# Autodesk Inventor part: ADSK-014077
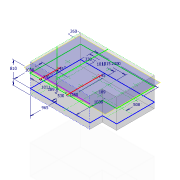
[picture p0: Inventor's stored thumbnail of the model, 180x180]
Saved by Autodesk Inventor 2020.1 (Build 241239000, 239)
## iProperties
Created: 2019-10
Part Number: ADSK-014077
Material: 1.0501 C35
Document SubType Name: Modeling
Designer: lutzd
Mass: 3.8576e+07 g
Surface Area: 188642 cm^2
Volume: 4.9204e+06 cm^3
Density: 7.84 g/cm^3
Appearance: Klar - Weiß
VLDS_Profile: Default Part
VLDS_TimeStamp: 2016-07-29
VLDS_FailCnt: 0
VLDS_AcceptCnt: 0
Dimensions: 2690x1830x1050 mm
Mass: 38575,975 kg
DocNumber: ADSK-014077
Folder: 01 - Themengebiete\Simplification\01 - Packaging machine\
VDS_Category: 3D Komponenten
VDS_NumSchm: Autodesk
Title: skeleton
Author: lutzd
Revision Number: -
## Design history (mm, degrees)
sketch "Skizze1"
  geometry: L1 (0, 0)-(0, 1830); L2 (0, 1830)-(2690, 1830); L3 (2690, 1830)-(2690, 455); L4 (2690, 455)-(2170, 455); L5 (2170, 455)-(2170, 0); L6 (2170, 0)-(0, 0)
  constraints: 12 end point, 5 perpendicular, 1 vertical
  dimensions: "d0" = 2690 distance of L1.end L2.end; "d1" = 1830 distance of L1.start L1.end; "d2" = 520 distance of L3.end L4.end; "d3" = 455 distance of L4.end L5.end
extrude "Extrusion1" new body sketch "Skizze1" distance "d4" = 1050; taper "d5" = 0 deg
sketch "Skizze2" dims "d12" = 1011
  geometry: L1 (0, 1050)-(2170, 1050) reference; L2 (0, 0)-(2170, 0) reference; L3 (2170, 0)-(2170, 1050) reference; L4 (0, 0)-(0, 1050) reference; L5 (0, 810)-(2170, 810); 1 further point
  constraints: 3 point on line, 2 end point, 1 perpendicular
  dimensions: "d24" = 810 distance between parallel lines of L5 L2; "d26" = 1011 distance from line of L4 point (1011, 810)
workplane "Arbeitsebene1"
sketch "Skizze4" dims "d12" = 1011
  geometry: L1 (1050, 1830)-(1050, 0) reference; L2 (0, 1830)-(0, 0) reference; L3 (1050, 965)-(0, 965); L4 (0, 0)-(1050, 0) reference
  constraints: 2 end point, 2 point on line, 1 perpendicular
  dimensions: "d14" = 965 distance between parallel lines of L4 L3
sketch "Skizze3"
  geometry: L1 (0, 0)-(-2170, 0) reference; L2 (-2170, 0)-(-2170, 455) reference; L3 (-2170, 455)-(-2690, 455) reference; L4 (-2690, 455)-(-2690, 1830) reference; L5 (-2690, 1830)-(0, 1830) reference; L6 (0, 1830)-(0, 0) reference; L7 (-330, 1830)-(-330, 0); L8 (-1315, 1830)-(-1315, 0); L9 (-2300, 1830)-(-2300, 1038); L10 (-330, 530)-(-1315, 530); L11 (-1011, 530)-(-1011, 1830); L12 (-1315, 1038)-(-2690, 1038); L13 (0, 965)-(-330, 965); L14 (0, 0)-(-2170, 0) reference; L15 (-2300, 1038)-(-2300, 455); 10 further points
  constraints: 21 point on line, 16 end point, 7 perpendicular, 2 coincident, 1 horizontal, 1 horizontal alignment
  dimensions: "d8" = 330 distance between parallel lines of L6 L7; "d9" = 1315 distance between parallel lines of L8 L6; "d10" = 2300 distance between parallel lines of L6 L9; "d11" = 530 distance between parallel lines of L10 L1; "d12" = 1011 distance between parallel lines of L11 L6; "d13" = 1038 distance between parallel lines of L12 L1; "d16" = 508 distance from line of point (-2300, 1546) L12; "d18" = 189 distance from line of L8 point (-1504, 1038); "d19" = 189 distance from line of L7 point (-519, 530); "d25" = 1038 distance from line of L1 point (-330, 1038)
  node "Schnittkanten projizieren1" dims "d12" = 1011
workplane "Arbeitsebene2"
workplane "Arbeitsebene3"
sketch "Skizze5" dims "d12" = 1011
  geometry: L1 (-1315, 1038)-(-2690, 1038) reference; L2 (-2300, 1830)-(-2300, 455) reference; L3 (-2170, 0)-(-2170, 455) reference; L4 (-2170, 455)-(-2690, 455) reference; L5 (-2690, 455)-(-2690, 1830) reference; L6 (-2690, 1830)-(0, 1830) reference; L7 (0, 1830)-(0, 0) reference; L8 (0, 0)-(-2170, 0) reference; 7 further points
  constraints: 2 point on line, 1 coincident
  node "Projizierte Kontur1" dims "d12" = 1011
sketch "Skizze6" dims "d12" = 1011
  geometry: L1 (2690, 1830)-(0, 1830) reference; L2 (0, 0)-(2170, 0) reference; L3 (0, 1830)-(0, 0) reference; L4 (1011, 0)-(1011, 1830); 1 further point
  constraints: 2 end point, 2 point on line, 1 perpendicular
  dimensions: "d22" = 260 distance from line of L1 point (0, 1570)
sketch "Skizze9" dims "d12" = 1011
  geometry: L1 (-519, 575)-(-519, -195); L2 (-1504, 1083)-(-1504, -197); 3 further points
  constraints: 4 end point, 2 point on line, 2 vertical
  dimensions: "d30" = 45 distance of point (-1504, 1038) L2.start; "d31" = 45 distance of point (-519, 530) L1.start; "d32" = 1280 distance of L2.start L2.end; "d33" = 770 distance of L1.start L1.end
node "Volumenkörper1"
feature "쀀䁆" dims "d12" = 1011
other parameters: "d15" = -695, "d29" = -845
